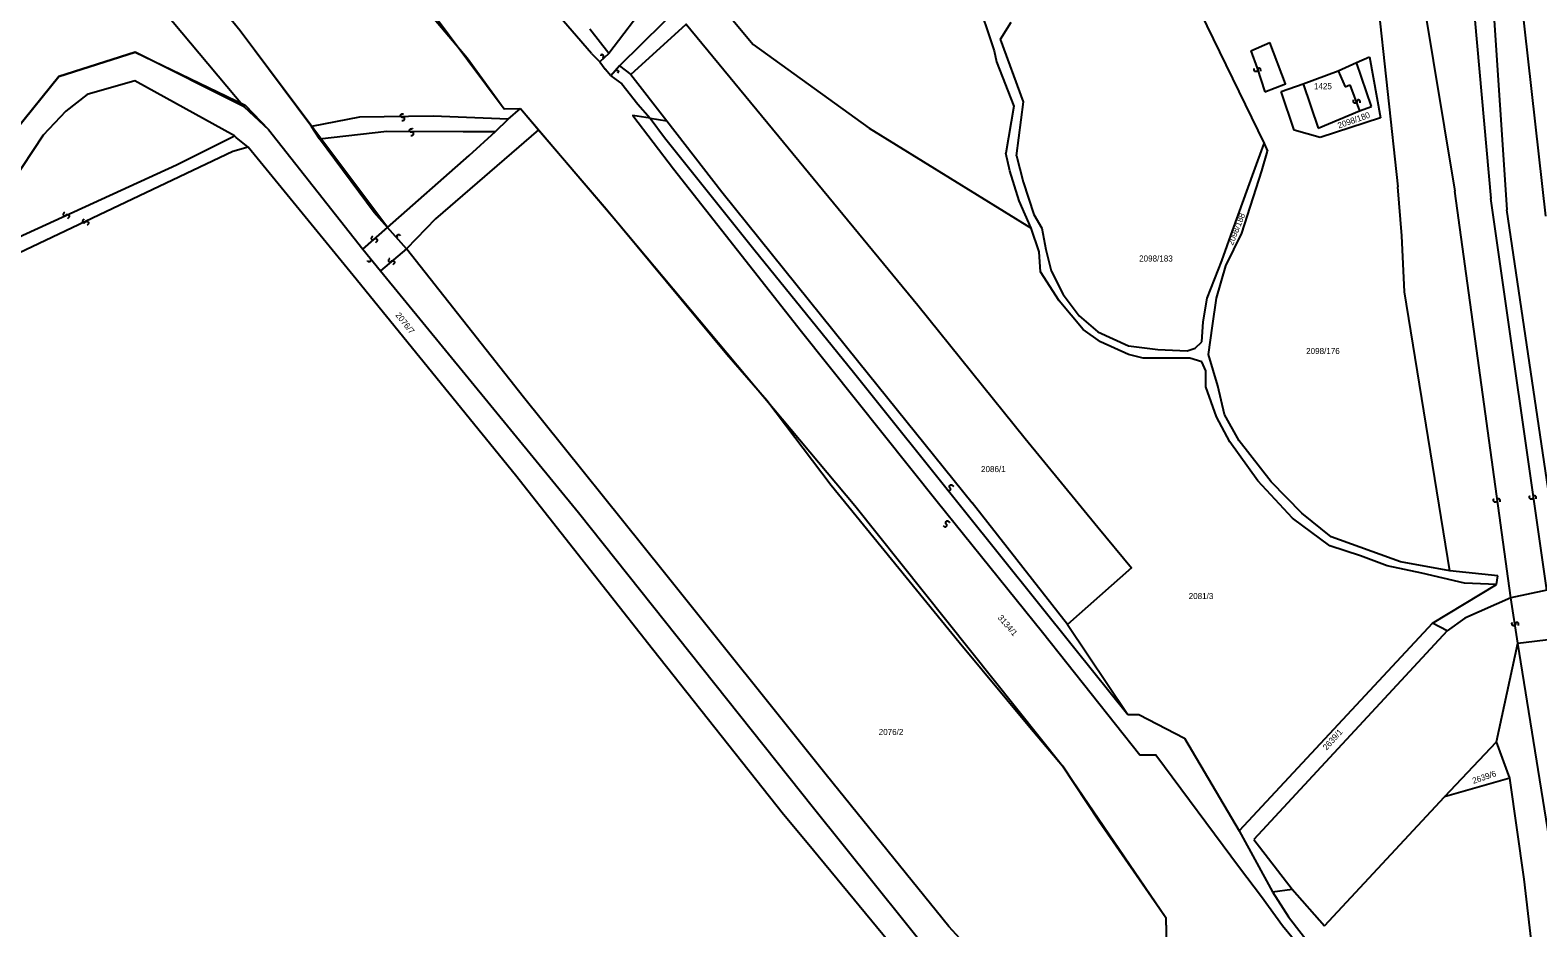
# Model space of a CAD drawing. Extents: x -581999 to -572728, y -1219553 to -1212032.
# Drawn here: x -576856.1 to -576356.3, y -1215847.9 to -1215550.3 of the extents above; entities that cross this region are included whole.
import ezdxf

# ---------------------------------------------------------------- set-up
doc = ezdxf.new("R2010")
doc.units = 0
for name, color, linetype in [('Vrstva 1', 7, 'Continuous'), ('Vrstva 2', 7, 'Continuous'), ('Vrstva 4', 7, 'Continuous'), ('Vrstva 6', 7, 'Continuous'), ('Vrstva 63', 7, 'Continuous')]:
    doc.layers.add(name, color=color, linetype=linetype)

msp = doc.modelspace()

# ---------------------------------------------------------------- linework, layer by layer
at = {"layer": 'Vrstva 1'}
for p, q in [((-576416.656, -1215473.31), (-576402.699, -1215602.274)), ((-576638.42, -1215528.539), (-576616.388, -1215555.07)), ((-576546.084, -1215528.202), (-576536.521, -1215557.161)), ((-576470.167, -1215540.164), (-576446.943, -1215587.831)), ((-576534.373, -1215553.234), (-576530.821, -1215547.596)), ((-576526.723, -1215573.992), (-576534.373, -1215553.234)), ((-576664.26, -1215558.033), (-576667.168, -1215560.749)), ((-576616.388, -1215555.07), (-576577.892, -1215582.753)), ((-576536.521, -1215557.161), (-576535.702, -1215560.749)), ((-576416.423, -1215560.956), (-576412.1, -1215559.084)), ((-576412.1, -1215559.084), (-576408.442, -1215579.358)), ((-576535.702, -1215560.749), (-576530.002, -1215575.53)), ((-576434.047, -1215568.129), (-576422.408, -1215563.763)), ((-576422.408, -1215563.763), (-576416.423, -1215560.956)), ((-576411.435, -1215575.615), (-576416.423, -1215560.956)), ((-576441.362, -1215570.624), (-576434.047, -1215568.129)), ((-576434.047, -1215568.129), (-576429.059, -1215582.789)), ((-576529.055, -1215591.914), (-576526.723, -1215573.992)), ((-576437.039, -1215583.412), (-576441.362, -1215570.624)), ((-576650.529, -1215579.473), (-576644.992, -1215580.31)), ((-576530.002, -1215575.53), (-576532.589, -1215591.085)), ((-576408.442, -1215579.358), (-576428.394, -1215585.908)), ((-576577.892, -1215582.753), (-576524.195, -1215615.95)), ((-576428.394, -1215585.908), (-576437.039, -1215583.412)), ((-576450.414, -1215597.301), (-576446.943, -1215587.831)), ((-576446.943, -1215587.831), (-576445.851, -1215590.394)), ((-576531.264, -1215596.887), (-576532.589, -1215591.085)), ((-576529.055, -1215591.914), (-576526.846, -1215600.617)), ((-576447.763, -1215596.887), (-576445.851, -1215590.394)), ((-576528.171, -1215606.833), (-576531.264, -1215596.887)), ((-576457.483, -1215616.778), (-576450.414, -1215597.301)), ((-576454.39, -1215617.607), (-576447.763, -1215596.887)), ((-576526.846, -1215600.617), (-576523.312, -1215611.391)), ((-576401.373, -1215618.436), (-576402.699, -1215602.274)), ((-576524.195, -1215615.95), (-576528.171, -1215606.833)), ((-576523.312, -1215611.391), (-576520.661, -1215615.95)), ((-576521.544, -1215623.823), (-576524.195, -1215615.95)), ((-576520.661, -1215615.95), (-576519.335, -1215622.994)), ((-576461.017, -1215626.724), (-576457.483, -1215616.778)), ((-576459.692, -1215628.382), (-576454.39, -1215617.607)), ((-576400.49, -1215637.084), (-576401.373, -1215618.436)), ((-576521.103, -1215630.454), (-576521.544, -1215623.823)), ((-576519.335, -1215622.994), (-576517.568, -1215630.039)), ((-576465.877, -1215639.156), (-576461.017, -1215626.724)), ((-576462.784, -1215639.156), (-576459.692, -1215628.382)), ((-576514.917, -1215639.985), (-576521.103, -1215630.454)), ((-576517.568, -1215630.039), (-576513.592, -1215637.913)), ((-576513.592, -1215637.913), (-576508.29, -1215644.958)), ((-576467.202, -1215647.03), (-576465.877, -1215639.156)), ((-576464.11, -1215648.273), (-576462.784, -1215639.156)), ((-576385.468, -1215729.496), (-576400.49, -1215637.084)), ((-576506.965, -1215649.516), (-576514.917, -1215639.985)), ((-576508.29, -1215644.958), (-576502.105, -1215650.345)), ((-576501.221, -1215653.66), (-576506.965, -1215649.516)), ((-576467.644, -1215653.66), (-576467.202, -1215647.03)), ((-576465.435, -1215657.804), (-576464.11, -1215648.273)), ((-576502.105, -1215650.345), (-576491.943, -1215654.903)), ((-576491.943, -1215657.804), (-576501.221, -1215653.66)), ((-576469.853, -1215655.732), (-576467.644, -1215653.66)), ((-576491.943, -1215654.903), (-576482.224, -1215656.147)), ((-576487.084, -1215659.047), (-576491.943, -1215657.804)), ((-576479.573, -1215659.047), (-576487.084, -1215659.047)), ((-576482.224, -1215656.147), (-576472.504, -1215656.561)), ((-576471.62, -1215659.047), (-576479.573, -1215659.047)), ((-576472.504, -1215656.561), (-576469.853, -1215655.732)), ((-576467.644, -1215660.291), (-576471.62, -1215659.047)), ((-576462.342, -1215668.164), (-576465.435, -1215657.804)), ((-576466.319, -1215663.192), (-576467.644, -1215660.291)), ((-576466.319, -1215668.579), (-576466.319, -1215663.192)), ((-576462.784, -1215678.524), (-576466.319, -1215668.579)), ((-576460.133, -1215677.696), (-576462.342, -1215668.164)), ((-576458.366, -1215686.812), (-576462.784, -1215678.524)), ((-576455.274, -1215686.398), (-576460.133, -1215677.696)), ((-576449.088, -1215699.659), (-576458.366, -1215686.812)), ((-576444.67, -1215700.073), (-576455.274, -1215686.398)), ((-576437.601, -1215712.091), (-576449.088, -1215699.659)), ((-576434.509, -1215710.433), (-576444.67, -1215700.073)), ((-576425.231, -1215721.208), (-576437.601, -1215712.091)), ((-576424.789, -1215718.307), (-576434.509, -1215710.433)), ((-576401.815, -1215726.595), (-576424.789, -1215718.307)), ((-576415.069, -1215724.523), (-576425.231, -1215721.208)), ((-576406.233, -1215727.838), (-576415.069, -1215724.523)), ((-576394.746, -1215730.325), (-576406.233, -1215727.838)), ((-576385.468, -1215729.496), (-576401.815, -1215726.595)), ((-576369.563, -1215731.154), (-576385.468, -1215729.496)), ((-576380.609, -1215733.64), (-576394.746, -1215730.325)), ((-576391.212, -1215746.901), (-576370.005, -1215734.054)), ((-576370.005, -1215734.054), (-576380.609, -1215733.64)), ((-576370.005, -1215734.054), (-576369.563, -1215731.154)), ((-576365.185, -1215738.479), (-576380.497, -1215745.215)), ((-576353.257, -1215735.993), (-576365.185, -1215738.479)), ((-576512.163, -1215747.342), (-576492.231, -1215777.135)), ((-576391.212, -1215746.901), (-576455.274, -1215815.692)), ((-576386.352, -1215749.387), (-576450.414, -1215818.593)), ((-576386.352, -1215749.387), (-576391.212, -1215746.901)), ((-576380.497, -1215745.215), (-576386.352, -1215749.387)), ((-576370.005, -1215786.269), (-576362.936, -1215753.531)), ((-576362.936, -1215753.531), (-576350.918, -1215752.035)), ((-576492.231, -1215777.135), (-576488.516, -1215777.145)), ((-576488.516, -1215777.145), (-576473.388, -1215785.026)), ((-576473.388, -1215785.026), (-576455.274, -1215815.692)), ((-576387.236, -1215804.503), (-576370.005, -1215786.269)), ((-576365.587, -1215798.287), (-576370.005, -1215786.269)), ((-576365.587, -1215798.287), (-576387.236, -1215804.503)), ((-576360.8, -1215831.766), (-576365.587, -1215798.287)), ((-576426.998, -1215847.186), (-576387.236, -1215804.503)), ((-576455.274, -1215815.692), (-576444.228, -1215835.997)), ((-576450.414, -1215818.593), (-576437.683, -1215835.044)), ((-576356.273, -1215870.335), (-576360.8, -1215831.766)), ((-576444.228, -1215835.997), (-576437.683, -1215835.044)), ((-576437.683, -1215835.044), (-576426.998, -1215847.186))]:
    msp.add_line(p, q, dxfattribs=at)
for points in [[(-576762.808, -1215582.263), (-576786.45, -1215550.556), (-576835.355, -1215490.234), (-576866.76, -1215451.363), (-576897.91, -1215423.983), (-576914.339, -1215414.57), (-576881.303, -1215373.144)], [(-576947.523, -1215456.201), (-576923.293, -1215425.212), (-576903.519, -1215431.029), (-576870.194, -1215469.135), (-576826.446, -1215526.328), (-576785.099, -1215575.711)], [(-576787.487, -1215469.72), (-576746.45, -1215517.684), (-576711.146, -1215559.491), (-576698.905, -1215576.332), (-576693.546, -1215576.246)], [(-576669.983, -1215558.026), (-576709.907, -1215511.86)], [(-576638.42, -1215528.539), (-576638.948, -1215540.719), (-576660.671, -1215562.057)], [(-576650.769, -1215534.809), (-576651.118, -1215540.789), (-576664.26, -1215558.033)], [(-576656.973, -1215565.011), (-576638.604, -1215548.282), (-576606.285, -1215587.458)], [(-576664.26, -1215558.033), (-576670.561, -1215549.999)], [(-576785.099, -1215575.711), (-576821.235, -1215557.57), (-576846.598, -1215565.67), (-576860.844, -1215583.271), (-576888.618, -1215632.553)], [(-576669.983, -1215558.026), (-576667.168, -1215560.749)], [(-576667.168, -1215560.749), (-576665.494, -1215563.216)], [(-576663.6, -1215565.407), (-576665.494, -1215563.216)], [(-576660.671, -1215562.057), (-576663.6, -1215565.407)], [(-576660.671, -1215562.057), (-576656.973, -1215565.011)], [(-576783.853, -1215589.079), (-576787.731, -1215585.86), (-576788.379, -1215585.281), (-576821.386, -1215567.085), (-576837.181, -1215571.648), (-576844.275, -1215577.087), (-576851.805, -1215585.045), (-576862.304, -1215600.977), (-576875.781, -1215626.143)], [(-576663.6, -1215565.407), (-576659.943, -1215568.098), (-576654.583, -1215574.803)], [(-576656.973, -1215565.011), (-576644.992, -1215580.31), (-576626.757, -1215603.912), (-576581.388, -1215660.297), (-576543.821, -1215706.961)], [(-576785.099, -1215575.711), (-576777.019, -1215583.253), (-576745.795, -1215622.875)], [(-576701.789, -1215583.923), (-576697.609, -1215579.739)], [(-576697.609, -1215579.739), (-576693.546, -1215576.246)], [(-576693.546, -1215576.246), (-576687.504, -1215583.327)], [(-576654.583, -1215574.803), (-576650.529, -1215579.473)], [(-576429.059, -1215582.789), (-576415.351, -1215576.997), (-576411.435, -1215575.615)], [(-576760.162, -1215586.277), (-576762.808, -1215582.263)], [(-576687.504, -1215583.327), (-576721.722, -1215612.809), (-576731.359, -1215622.733)], [(-576710.556, -1215591.871), (-576701.789, -1215583.923)], [(-576687.504, -1215583.327), (-576665.077, -1215609.464), (-576625.092, -1215657.66), (-576611.895, -1215672.991), (-576590.552, -1215701.14)], [(-576606.329, -1215810.331), (-576649.766, -1215755.451), (-576695.152, -1215697.864), (-576749.009, -1215631.628), (-576783.853, -1215589.079)], [(-576737.619, -1215615.655), (-576742.078, -1215610.689), (-576760.162, -1215586.277)], [(-576606.285, -1215587.458), (-576561.776, -1215641.489), (-576526.257, -1215685.638), (-576502.182, -1215715.053)], [(-576737.619, -1215615.655), (-576710.556, -1215591.871)], [(-576731.359, -1215622.733), (-576737.619, -1215615.655)], [(-576745.795, -1215622.875), (-576739.951, -1215630.112)], [(-576479.285, -1215859.89), (-576485.187, -1215866.742), (-576484.603, -1215882.897), (-576527.82, -1215868.951), (-576536.952, -1215863.368), (-576551.478, -1215847.449), (-576592.142, -1215797.154), (-576646.228, -1215729.634), (-576692.543, -1215671.933), (-576731.359, -1215622.733)], [(-576739.951, -1215630.112), (-576674.27, -1215710.246), (-576596.364, -1215808.053), (-576545.842, -1215871.151), (-576536.296, -1215876.947)], [(-576590.552, -1215701.14), (-576548.112, -1215753.21), (-576524.714, -1215781.345), (-576513.837, -1215794.187), (-576501.841, -1215812.382), (-576479.554, -1215844.465), (-576479.285, -1215859.89)], [(-576502.182, -1215715.053), (-576490.914, -1215728.553), (-576512.163, -1215747.342), (-576543.821, -1215706.961)], [(-576545.048, -1215882.325), (-576565.588, -1215859.563), (-576598.503, -1215819.713), (-576606.329, -1215810.331)], [(-576444.228, -1215835.997), (-576438.927, -1215844.286)], [(-576438.927, -1215844.286), (-576430.533, -1215855.06)]]:
    msp.add_lwpolyline(points, dxfattribs=at)
at = {"layer": 'Vrstva 4'}
for p, q in [((-576363.252, -1215526.638), (-576353.704, -1215611.911)), ((-576394.723, -1215537.696), (-576383.746, -1215603.623)), ((-576371.153, -1215540.221), (-576366.516, -1215609.839)), ((-576377.141, -1215546.937), (-576371.818, -1215606.109)), ((-576422.408, -1215563.763), (-576420.19, -1215569.016)), ((-576420.19, -1215569.016), (-576418.629, -1215568.39)), ((-576418.629, -1215568.39), (-576415.351, -1215576.997)), ((-576365.185, -1215738.479), (-576383.746, -1215603.623)), ((-576353.257, -1215735.993), (-576371.818, -1215606.109)), ((-576347.955, -1215735.164), (-576366.516, -1215609.839)), ((-576546.733, -1215709.048), (-576509.765, -1215755.308)), ((-576362.936, -1215753.531), (-576365.185, -1215738.479)), ((-576351.456, -1215824.892), (-576362.936, -1215753.531)), ((-576509.765, -1215755.308), (-576492.231, -1215777.135))]:
    msp.add_line(p, q, dxfattribs=at)
for points in [[(-576451.405, -1215557.12), (-576445.096, -1215554.393)], [(-576446.804, -1215570.701), (-576439.956, -1215568.045), (-576445.096, -1215554.393)], [(-576451.405, -1215557.12), (-576449.28, -1215562.837)], [(-576449.28, -1215562.837), (-576446.804, -1215570.701)], [(-576697.609, -1215579.739), (-576722.448, -1215578.805), (-576746.891, -1215579.134), (-576762.808, -1215582.263)], [(-576650.529, -1215579.473), (-576656.316, -1215578.611), (-576642.823, -1215596.297), (-576600.311, -1215650.166), (-576555.385, -1215706.506)], [(-576650.529, -1215579.473), (-576645.728, -1215585.878)], [(-576760.162, -1215586.277), (-576737.818, -1215583.789), (-576712.555, -1215583.883)], [(-576712.555, -1215583.883), (-576701.789, -1215583.923)], [(-576783.853, -1215589.079), (-576788.828, -1215590.54), (-576879.989, -1215633.692)], [(-576875.781, -1215626.143), (-576807.527, -1215594.875), (-576788.379, -1215585.281)], [(-576645.728, -1215585.878), (-576616.18, -1215622.837), (-576583.074, -1215663.647), (-576546.733, -1215709.048)], [(-576745.795, -1215622.875), (-576737.619, -1215615.655)], [(-576731.359, -1215622.733), (-576739.951, -1215630.112)], [(-576555.385, -1215706.506), (-576520.446, -1215749.831), (-576488.24, -1215790.545), (-576482.874, -1215790.559), (-576455.197, -1215827.883), (-576447.871, -1215837.525), (-576440.959, -1215847.164), (-576433.628, -1215855.966), (-576413.691, -1215881.523)]]:
    msp.add_lwpolyline(points, dxfattribs=at)
at = {"layer": 'Vrstva 6'}
for points, degree in [([(-576666.104, -1215559.513), (-576665.753, -1215558.734), (-576666.381, -1215558.306), (-576666.757, -1215558.447), (-576666.871, -1215558.695), (-576666.936, -1215558.796)], 3), ([(-576662.213, -1215563.751), (-576661.483, -1215563.305), (-576660.98, -1215563.875), (-576661.074, -1215564.265), (-576661.306, -1215564.409), (-576661.398, -1215564.486)], 3), ([(-576448.143, -1215563.917), (-576448.048, -1215563.066), (-576448.778, -1215562.854), (-576449.095, -1215563.108), (-576449.14, -1215563.524), (-576449.291, -1215563.831), (-576449.54, -1215563.998), (-576449.767, -1215564.042), (-576450.03, -1215563.986), (-576450.285, -1215563.722), (-576450.325, -1215563.112), (-576450.255, -1215562.943)], 2), ([(-576415.206, -1215574.401), (-576415.111, -1215573.55), (-576415.841, -1215573.338), (-576416.158, -1215573.592), (-576416.203, -1215574.008), (-576416.354, -1215574.315), (-576416.603, -1215574.482), (-576416.83, -1215574.526), (-576417.093, -1215574.47), (-576417.348, -1215574.206), (-576417.388, -1215573.596), (-576417.318, -1215573.427)], 2), ([(-576732.804, -1215580.268), (-576731.953, -1215580.179), (-576731.901, -1215579.421), (-576732.217, -1215579.165), (-576732.633, -1215579.21), (-576732.965, -1215579.128), (-576733.182, -1215578.92), (-576733.273, -1215578.708), (-576733.274, -1215578.439), (-576733.071, -1215578.134), (-576732.483, -1215577.964), (-576732.303, -1215577.997)], 2), ([(-576729.833, -1215585.215), (-576728.982, -1215585.126), (-576728.93, -1215584.368), (-576729.246, -1215584.112), (-576729.662, -1215584.157), (-576729.994, -1215584.075), (-576730.211, -1215583.867), (-576730.302, -1215583.655), (-576730.303, -1215583.386), (-576730.1, -1215583.081), (-576729.512, -1215582.911), (-576729.332, -1215582.944)], 2), ([(-576844.73, -1215610.625), (-576845.317, -1215611.247), (-576844.862, -1215611.856), (-576844.456, -1215611.844), (-576844.17, -1215611.539), (-576843.864, -1215611.385), (-576843.564, -1215611.401), (-576843.357, -1215611.503), (-576843.181, -1215611.706), (-576843.136, -1215612.07), (-576843.471, -1215612.582), (-576843.629, -1215612.674)], 2), ([(-576838.3, -1215612.883), (-576838.887, -1215613.505), (-576838.432, -1215614.114), (-576838.026, -1215614.102), (-576837.74, -1215613.797), (-576837.434, -1215613.643), (-576837.134, -1215613.659), (-576836.927, -1215613.761), (-576836.751, -1215613.964), (-576836.706, -1215614.328), (-576837.041, -1215614.84), (-576837.199, -1215614.932)], 2), ([(-576742.594, -1215618.598), (-576743.181, -1215619.22), (-576742.726, -1215619.829), (-576742.32, -1215619.817), (-576742.034, -1215619.512), (-576741.728, -1215619.358), (-576741.428, -1215619.374), (-576741.221, -1215619.476), (-576741.045, -1215619.679), (-576741, -1215620.043), (-576741.335, -1215620.555), (-576741.493, -1215620.647)], 2), ([(-576734.344, -1215619.094), (-576734.62, -1215618.285), (-576733.954, -1215617.918), (-576733.594, -1215618.094), (-576733.503, -1215618.352), (-576733.448, -1215618.459)], 3), ([(-576743.284, -1215626.092), (-576743.043, -1215626.912), (-576743.724, -1215627.249), (-576744.076, -1215627.058), (-576744.156, -1215626.796), (-576744.206, -1215626.687)], 3), ([(-576736.887, -1215625.928), (-576737.474, -1215626.55), (-576737.019, -1215627.159), (-576736.613, -1215627.147), (-576736.327, -1215626.842), (-576736.021, -1215626.688), (-576735.721, -1215626.704), (-576735.514, -1215626.806), (-576735.338, -1215627.009), (-576735.293, -1215627.373), (-576735.628, -1215627.885), (-576735.786, -1215627.977)], 2), ([(-576552.142, -1215702.484), (-576551.566, -1215703.116), (-576550.924, -1215702.709), (-576550.905, -1215702.303), (-576551.188, -1215701.995), (-576551.318, -1215701.678), (-576551.279, -1215701.38), (-576551.162, -1215701.181), (-576550.946, -1215701.021), (-576550.58, -1215701.004), (-576550.095, -1215701.377), (-576550.015, -1215701.542)], 2), ([(-576356.829, -1215705.687), (-576356.734, -1215704.836), (-576357.464, -1215704.624), (-576357.781, -1215704.878), (-576357.826, -1215705.294), (-576357.977, -1215705.601), (-576358.226, -1215705.768), (-576358.453, -1215705.812), (-576358.716, -1215705.756), (-576358.971, -1215705.492), (-576359.011, -1215704.882), (-576358.941, -1215704.713)], 2), ([(-576368.778, -1215706.662), (-576368.683, -1215705.811), (-576369.413, -1215705.599), (-576369.73, -1215705.853), (-576369.775, -1215706.269), (-576369.926, -1215706.576), (-576370.175, -1215706.743), (-576370.402, -1215706.787), (-576370.665, -1215706.731), (-576370.92, -1215706.467), (-576370.96, -1215705.857), (-576370.89, -1215705.688)], 2), ([(-576553.399, -1215714.459), (-576552.823, -1215715.091), (-576552.181, -1215714.684), (-576552.162, -1215714.278), (-576552.445, -1215713.97), (-576552.575, -1215713.653), (-576552.536, -1215713.355), (-576552.419, -1215713.156), (-576552.203, -1215712.996), (-576551.837, -1215712.979), (-576551.352, -1215713.352), (-576551.272, -1215713.517)], 2), ([(-576362.665, -1215747.609), (-576362.57, -1215746.758), (-576363.3, -1215746.546), (-576363.617, -1215746.8), (-576363.662, -1215747.216), (-576363.813, -1215747.523), (-576364.062, -1215747.69), (-576364.289, -1215747.734), (-576364.552, -1215747.678), (-576364.807, -1215747.414), (-576364.847, -1215746.804), (-576364.777, -1215746.635)], 2)]:
    msp.add_open_spline(points, degree=degree, dxfattribs=at)
at = {"layer": 'Vrstva 63'}
for p, q in [((-576786.45, -1215550.556), (-576866.76, -1215451.363)), ((-576722.974, -1215544.138), (-576698.905, -1215576.332)), ((-576737.619, -1215615.655), (-576786.45, -1215550.556)), ((-576846.598, -1215565.67), (-576821.235, -1215557.57)), ((-576821.235, -1215557.57), (-576784.837, -1215575.193)), ((-576860.844, -1215583.271), (-576846.598, -1215565.67)), ((-576784.837, -1215575.193), (-576777.019, -1215583.253)), ((-576698.905, -1215576.332), (-576693.546, -1215576.246)), ((-576693.546, -1215576.246), (-576661.288, -1215614.167)), ((-576777.019, -1215583.253), (-576745.795, -1215622.875)), ((-576661.288, -1215614.167), (-576582.737, -1215707.852)), ((-576745.795, -1215622.875), (-576737.619, -1215615.655)), ((-576582.737, -1215707.852), (-576513.837, -1215794.187)), ((-576513.837, -1215794.187), (-576479.554, -1215844.465)), ((-576479.554, -1215844.465), (-576479.285, -1215859.89))]:
    msp.add_line(p, q, dxfattribs=at)

# ---------------------------------------------------------------- texts
at = {"layer": 'Vrstva 2'}
for s, p in [('1425', (-576430.489, -1215569.852)), ('2098/183', (-576488.438, -1215626.981)), ('2098/176', (-576433.076, -1215657.65)), ('2086/1', (-576540.854, -1215696.802)), ('2081/3', (-576472.015, -1215738.891)), ('2076/2', (-576574.78, -1215783.945))]:
    msp.add_text(s, height=2, dxfattribs=at).set_placement(p)
for s, rotation, p in [('2098/180', 19.48746, (-576422.205, -1215582.918)), ('2098/188', 68.12214, (-576457.363, -1215621.793)), ('2076/7', 308.33444, (-576735.111, -1215644.795)), ('3134/1', 310.89445, (-576535.45, -1215745.168)), ('2639/1', 47.80704, (-576426.3, -1215789.149)), ('2639/6', 18.52409, (-576377.6, -1215800.164))]:
    msp.add_text(s, height=2, rotation=rotation, dxfattribs=at).set_placement(p)

doc.saveas('drawing.dxf')
